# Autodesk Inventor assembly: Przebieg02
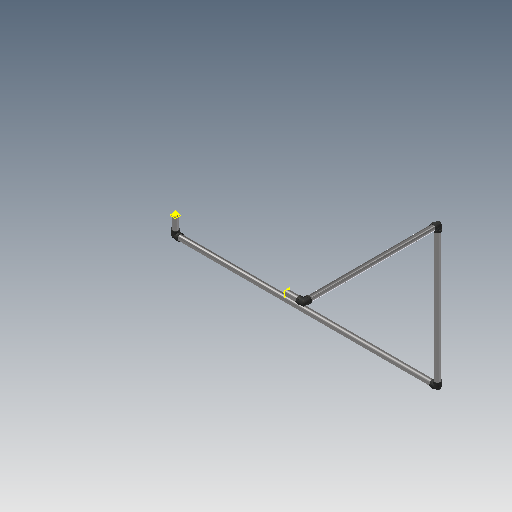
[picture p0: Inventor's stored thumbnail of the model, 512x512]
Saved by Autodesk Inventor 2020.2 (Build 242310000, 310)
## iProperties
Name: JIS G 3458/JIS B 2316 - Rury stalowe spawane i łączniki
ActiveState: True
PipeType: Rigid Pipe
Material: UnInitValue
Standard: UnInitValue
FittingMaterial: UnInitValue
FittingStandard: UnInitValue
RouteDirection90: True
RouteDirection45: True
IsFlanged: False
IsButtWelded: False
DiameterType: Nominal
Diameter: M40
Schedule: 80
OD: UnInitValue
ID: UnInitValue
Ending: UnInitValue
IntermediateSegmentsMin: 60,000 mm
IntermediateSegmentsMax: 5000,000 mm
IntermediateSegmentsInc: 1,000 mm
TerminationSegmentsMin: 60,000 mm
TerminationSegmentsMax: 5000,000 mm
TerminationSegmentsInc: 1,000 mm
RoundUpValue: UnInitValue
PipingComponentColor: As Material
PipeKey: v3#da14b0ab-0b36-4851-8d66-8c9cd0bcbe86#23
CouplingKey: v3#12b64993-10e6-4915-8315-0c0cce209ad0#8
Elbow90Key: v3#1f65ece3-c41a-48d4-8661-909ed34ade86#8
Elbow45Key: v3#28e76e79-e22c-40ab-8be2-ff545b1407c5#8
FlangeKey: UnInitValue
GasketKey: UnInitValue
Gap: UnInitValue
_ComponentInfo: <CS><C N="Pipe" R="2.430000" IR="1.920000" PL="PL" PN="JIS G 3458 Pipe 40 A x Sch 80"><CO N="1"><FE V="0"/><FD V="1"/><ET V="Welded"/><NS V="M40"/><MA V="0.0000
ShowGap: UnInitValue
MixedUnits: False
UseFlangsForCouplings: UnInitValue
IsSelfDraining: False
ElbowCustomKey: UnInitValue
Manager: www.cadconsulting.pl
Company: Fabian Stasiak CAD Consulting
Created: 2014-08
Part Number: Przebieg02
Document SubType Name: Assembly
Designer: F.Stasiak
Catalog Web Link: www.expertbooks.pl
Author: F.Stasiak
Subject: Zbiór ćwiczeń. Autodesk Inventor 2020. Kurs Professional
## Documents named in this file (8)
- C:\2020_Kurs_Professional\R1 Rury\Trasa sztywna_4\AIP\Przewody rurowe\Przebieg02\Trasa sztywna_4.Przebieg02.iam
- C:\2020_Kurs_Professional\R1 Rury\Trasa sztywna_4\AIP\Przewody rurowe\Przebieg02\Trasa sztywna_4.Trasa02.ipt
- C:\2020_Kurs_Professional\R1 Rury\Trasa sztywna_4\AIP\Przewody rurowe\Przebieg02\pipipe.1406895929724.ipt
- C:\2020_Kurs_Professional\R1 Rury\Trasa sztywna_4\AIP\Przewody rurowe\Przebieg02\pipipe.1406895929852.ipt
- C:\2020_Kurs_Professional\R1 Rury\Trasa sztywna_4\AIP\Przewody rurowe\Przebieg02\pipipe.1406895929925.ipt
- C:\2020_Kurs_Professional\R1 Rury\Trasa sztywna_4\AIP\Przewody rurowe\Przebieg02\pipipe.1406895929979.ipt
- C:\2020_Kurs_Professional\Zasoby\ContentCenter\pl-PL\JIS B 2316 90 (1)\JIS B 2316 Kolano 90 stopni 40A x Sch 80.ipt
- C:\2020_Kurs_Professional\R1 Rury\Trasa sztywna_4\AIP\Przewody rurowe\Przebieg02\pipipe.1426676391988.ipt
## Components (10 placed, 7 different names)
1. Trasa02
2. Segment rurowy 1:1
3. JIS B 2316 Kolano 90 stopni 40A x Sch 80:1
4. Segment rurowy 7:1
5. JIS B 2316 Kolano 90 stopni 40A x Sch 80:2
6. Segment rurowy 3:1
7. JIS B 2316 Kolano 90 stopni 40A x Sch 80:3
8. Segment rurowy 4:1
9. JIS B 2316 Kolano 90 stopni 40A x Sch 80:4
10. Segment rurowy 5:1
